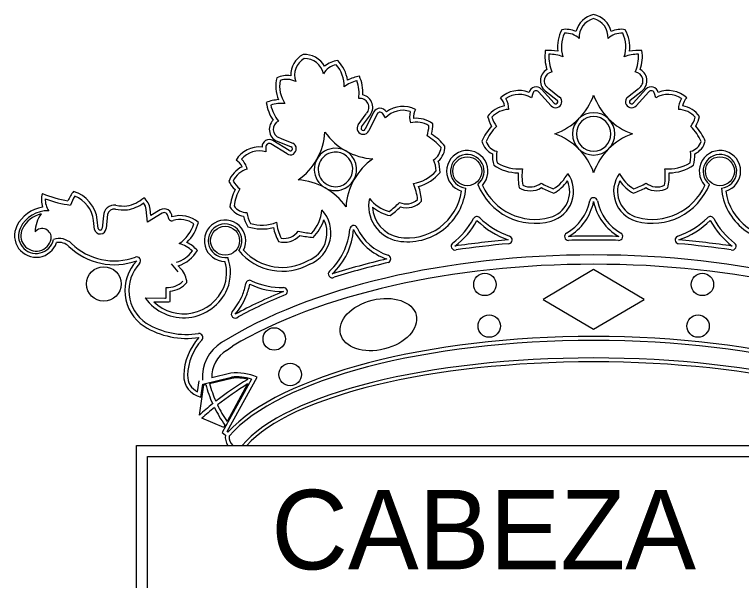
# Model space of a CAD drawing. Extents: x 0.2 to 61.3, y -17.9 to -0.8.
# Drawn here: x 32.52 to 40.48, y -7.03 to -0.84 of the extents above; entities that cross this region are included whole.
import ezdxf

# ---------------------------------------------------------------- set-up
doc = ezdxf.new("R2010")
doc.units = 0
doc.layers.add('Nivel 1', color=7, linetype='Continuous')

msp = doc.modelspace()

# ---------------------------------------------------------------- linework, layer by layer
at = {"layer": 'Nivel 1'}
for p, q in [((38.4267, -1.807), (38.2877, -1.6535)), ((38.3707, -1.6482), (38.4879, -1.7396)), ((39.2317, -1.7396), (39.3489, -1.6482)), ((39.4319, -1.6535), (39.2929, -1.807)), ((38.1935, -1.7018), (38.1784, -1.7493)), ((38.3955, -1.8359), (38.2561, -1.6821)), ((38.3445, -1.6818), (38.4609, -1.7725)), ((39.2586, -1.7725), (39.3751, -1.6818)), ((39.4635, -1.6821), (39.3241, -1.8359)), ((39.5412, -1.7493), (39.5261, -1.7018)), ((36.4532, -1.9053), (36.3611, -2.0907)), ((36.2839, -2.0425), (36.3718, -1.9227)), ((36.3188, -2.0669), (36.4061, -1.9479)), ((36.4913, -1.9242), (36.399, -2.1101)), ((36.5843, -1.9678), (36.5569, -1.9262)), ((35.5274, -2.3261), (35.352, -2.2161)), ((35.4304, -2.1885), (35.5681, -2.2446)), ((35.2745, -2.2882), (35.2729, -2.338)), ((35.5053, -2.3624), (35.3294, -2.2522)), ((35.4144, -2.2279), (35.5511, -2.2836)), ((33.5427, -3.0218), (33.5271, -3.1781)), ((33.9803, -3.1079), (33.9654, -2.9701)), ((34.139, -3.0102), (33.9803, -3.1079)), ((34.0154, -3.0363), (34.0077, -2.9655)), ((34.1166, -2.974), (34.0154, -3.0363)), ((33.399, -3.1867), (33.3875, -3.0881)), ((33.4409, -3.1786), (33.4298, -3.0832)), ((33.498, -3.0404), (33.4847, -3.1738)), ((34.3156, -3.6496), (34.2413, -3.5645)), ((34.3476, -3.6216), (34.3159, -3.5852)), ((38.8598, -3.6272), (38.3068, -3.9523)), ((39.4128, -3.9523), (38.8598, -3.6272)), ((34.1843, -3.937), (34.1843, -3.8215)), ((34.2269, -3.9765), (34.2269, -3.8626)), ((33.9534, -3.9363), (34.1681, -3.9372)), ((38.3068, -3.9523), (38.8598, -4.2775)), ((38.8598, -4.2775), (39.4128, -3.9523)), ((34.0472, -3.9793), (34.1679, -3.9798)), ((34.8436, -4.5104), (34.9084, -4.4629)), ((34.8915, -4.7588), (34.6815, -4.8099)), ((34.5275, -4.9636), (34.5452, -4.8431)), ((34.5831, -4.8777), (34.8987, -4.8008)), ((34.6577, -4.8727), (34.9009, -4.8134)), ((35.1174, -4.8251), (34.7977, -5.4074)), ((34.8517, -5.3975), (35.1782, -4.8028)), ((34.5462, -5.2184), (34.5945, -4.8881)), ((34.5623, -5.0205), (34.5831, -4.8777)), ((34.5945, -4.8881), (34.6163, -4.8828)), ((35.0743, -4.877), (34.8495, -5.2865)), ((34.8134, -5.3523), (34.5736, -5.251)), ((34.8267, -5.3281), (34.8134, -5.3523)), ((34.7977, -5.4074), (34.8309, -5.4357)), ((34.8592, -5.4039), (34.8517, -5.3975)), ((33.8598, -16.2496), (33.8598, -5.5507)), ((33.8598, -5.5507), (38.8598, -5.5507)), ((34.8577, -5.5507), (35.0647, -5.5507)), ((34.9113, -5.5507), (35.0139, -5.5507)), ((38.8598, -5.5507), (43.8598, -5.5507)), ((33.979, -16.2496), (33.979, -5.6699)), ((33.979, -5.6699), (38.8598, -5.6699)), ((38.8598, -5.6699), (43.7406, -5.6699))]:
    msp.add_line(p, q, dxfattribs=at)
for centre, radius in [((37.478, -2.5512), 0.1584), ((40.2416, -2.5512), 0.1584), ((34.828, -3.311), 0.1584), ((33.5008, -3.7837), 0.1891), ((37.6701, -3.7885), 0.1227), ((40.0495, -3.7885), 0.1227), ((37.7177, -4.2436), 0.1227), ((40.0019, -4.2436), 0.1227), ((35.3655, -4.3852), 0.1227), ((35.5396, -4.7737), 0.1227)]:
    msp.add_circle(centre, radius, dxfattribs=at)
for centre, radius, start, end in [((38.9122, -1.0852), 0.2528, 101.96797, 166.02665), ((38.8074, -1.0852), 0.2528, 13.97335, 78.03203), ((38.9122, -1.0852), 0.2102, 104.43964, 183.9233), ((38.8074, -1.0852), 0.2102, 356.0767, 75.56036), ((38.8484, -1.1913), 0.3844, 150.73287, 187.13746), ((38.5576, -1.253), 0.2535, 64.46311, 100.1151), ((39.162, -1.253), 0.2535, 79.8849, 115.53689), ((38.8712, -1.1913), 0.3844, 352.86254, 29.26713), ((38.8484, -1.1913), 0.3418, 154.23185, 198.42348), ((38.5576, -1.253), 0.211, 46.62254, 94.62972), ((39.162, -1.253), 0.211, 85.37028, 133.37746), ((38.8712, -1.1913), 0.3418, 341.57652, 25.76815), ((38.8024, -1.2947), 0.4759, 172.40101, 197.75384), ((38.3738, -1.7056), 0.4757, 78.71145, 95.19619), ((39.3458, -1.7056), 0.4757, 84.80381, 101.28855), ((38.9172, -1.2947), 0.4759, 342.24616, 7.59899), ((35.7987, -1.4996), 0.2528, 117.73147, 181.79015), ((35.7987, -1.4996), 0.2102, 120.20314, 199.68681), ((35.6977, -1.5281), 0.2528, 29.73686, 93.79553), ((35.6977, -1.5281), 0.2102, 11.8402, 91.32386), ((36.0846, -1.5931), 0.2535, 95.6484, 131.30039), ((35.788, -1.6128), 0.3844, 8.62605, 45.03063), ((38.8024, -1.2947), 0.4333, 177.05207, 203.25606), ((38.3738, -1.7056), 0.4331, 69.70422, 90.54379), ((39.3458, -1.7056), 0.4331, 89.45621, 110.29578), ((38.9172, -1.2947), 0.4333, 336.74394, 2.94793), ((36.0846, -1.5931), 0.211, 101.13378, 149.14096), ((35.788, -1.6128), 0.3418, 357.34003, 41.53165), ((35.5029, -1.7573), 0.2535, 80.22661, 115.8786), ((38.4168, -1.5622), 0.1397, 118.90053, 238.8754), ((38.4168, -1.5622), 0.0971, 97.33817, 238.8754), ((39.3028, -1.5622), 0.0971, 301.1246, 82.66183), ((39.3028, -1.5622), 0.1397, 301.1246, 61.09947), ((35.766, -1.619), 0.3844, 166.49637, 202.90096), ((35.766, -1.619), 0.3418, 169.99536, 214.18698), ((35.5029, -1.7573), 0.211, 62.38604, 110.39322), ((36.3844, -1.9788), 0.4331, 105.21971, 126.05928), ((36.3844, -1.9788), 0.4757, 100.56731, 117.05205), ((35.8603, -1.6998), 0.4333, 352.50744, 18.71143), ((35.8603, -1.6998), 0.4759, 358.00966, 23.36249), ((38.0443, -1.9646), 0.2962, 68.51354, 133.41957), ((38.2301, -1.7088), 0.0798, 43.83208, 165.5943), ((39.4895, -1.7088), 0.0798, 14.4057, 136.16792), ((39.6753, -1.9646), 0.2962, 46.58043, 111.48646), ((36.3041, -1.8524), 0.1397, 316.88811, 76.86297), ((37.729, -1.8627), 0.1591, 9.23351, 45.41392), ((38.0443, -1.9646), 0.2537, 58.06833, 124.65139), ((38.2301, -1.7088), 0.0372, 43.83208, 169.19164), ((38.4448, -1.7908), 0.0669, 222.4372, 49.9247), ((38.2071, -1.4896), 0.6915, 289.27044, 340.72956), ((39.5125, -1.4896), 0.6915, 199.27044, 250.72956), ((39.2748, -1.7908), 0.0669, 130.0753, 317.5628), ((39.4895, -1.7088), 0.0372, 10.80836, 136.16792), ((39.6753, -1.9646), 0.2537, 55.34861, 121.93167), ((39.9906, -1.8627), 0.1591, 134.58608, 170.76649), ((35.449, -2.2428), 0.4757, 94.47496, 110.95969), ((35.7499, -1.731), 0.4759, 188.16452, 213.51734), ((35.449, -2.2428), 0.4331, 85.46772, 106.30729), ((35.7499, -1.731), 0.4333, 192.81558, 219.01956), ((36.3041, -1.8524), 0.0971, 316.88811, 98.42534), ((37.729, -1.8627), 0.2017, 356.42911, 31.97613), ((38.4448, -1.7908), 0.0243, 221.73779, 48.52076), ((39.2748, -1.7908), 0.0243, 131.47924, 318.26221), ((39.9906, -1.8627), 0.2017, 148.02387, 183.57089), ((36.5236, -1.9428), 0.0798, 30.16921, 151.93143), ((36.5236, -1.9428), 0.0372, 26.57186, 151.93143), ((36.7719, -2.1385), 0.2537, 71.11211, 137.69518), ((36.7719, -2.1385), 0.2962, 62.34394, 127.24996), ((37.0477, -1.9548), 0.2017, 163.78738, 199.33439), ((37.0477, -1.9548), 0.1591, 150.34958, 186.53), ((37.9384, -2.1314), 0.2988, 100.09223, 142.84596), ((37.9384, -2.1314), 0.2562, 91.81464, 138.26352), ((39.7812, -2.1314), 0.2562, 41.73648, 88.18536), ((39.7812, -2.1314), 0.2988, 37.15404, 79.90777), ((36.9192, -2.2703), 0.2988, 52.91755, 95.67127), ((38.1073, -1.8494), 0.4195, 194.00616, 209.65395), ((38.1073, -1.8494), 0.377, 197.19431, 214.34916), ((38.8598, -2.1423), 0.2316, 90, 270), ((38.8598, -2.1423), 0.1891, 90, 270), ((38.8598, -2.1423), 0.2316, 270, 90), ((38.8598, -2.1423), 0.1891, 270, 90), ((39.6123, -1.8494), 0.377, 325.65084, 342.80569), ((39.6123, -1.8494), 0.4195, 330.34605, 345.99384), ((35.4514, -2.0932), 0.1397, 134.66404, 254.6389), ((35.4514, -2.0932), 0.0971, 113.10167, 254.6389), ((36.3392, -2.0801), 0.0669, 145.83881, 333.3263), ((36.3392, -2.0801), 0.0243, 147.24275, 334.02571), ((36.9192, -2.2703), 0.2562, 57.49999, 103.94886), ((36.68, -2.0448), 0.377, 341.41434, 358.56919), ((36.68, -2.0448), 0.4195, 346.10955, 1.75735), ((38.2089, -2.4676), 0.6213, 138.62593, 156.82666), ((38.2089, -2.4676), 0.5788, 135.51275, 155.29285), ((39.5107, -2.4676), 0.5788, 24.70715, 44.48725), ((39.5107, -2.4676), 0.6213, 23.17334, 41.37407), ((35.2298, -2.0803), 0.6915, 305.03394, 356.49306), ((36.4862, -1.7256), 0.6915, 215.03394, 266.49306), ((36.7501, -2.6674), 0.6213, 38.93684, 57.13757), ((38.2071, -2.795), 0.6915, 19.27044, 70.72956), ((39.5125, -2.795), 0.6915, 109.27044, 160.72956), ((35.3116, -2.285), 0.0798, 59.59558, 181.3578), ((36.7501, -2.6674), 0.5788, 40.47065, 60.25076), ((37.8457, -2.1669), 0.2154, 195.13329, 244.65872), ((37.8457, -2.1669), 0.1728, 199.90196, 254.34899), ((39.8739, -2.1669), 0.1728, 285.65101, 340.09804), ((39.8739, -2.1669), 0.2154, 295.34128, 344.86671), ((35.2022, -2.5816), 0.2962, 84.27704, 149.18307), ((35.3116, -2.285), 0.0372, 59.59558, 184.95514), ((35.5405, -2.3055), 0.0669, 238.20071, 65.6882), ((35.5405, -2.3055), 0.0243, 237.50129, 64.28426), ((36.0354, -2.5311), 0.2316, 285.7635, 105.7635), ((37.018, -2.2793), 0.1728, 301.41452, 355.86154), ((37.018, -2.2793), 0.2154, 311.10478, 0.63021), ((35.2022, -2.5816), 0.2537, 73.83183, 140.41489), ((36.0354, -2.5311), 0.2316, 105.7635, 285.7635), ((36.0354, -2.5311), 0.1891, 105.7635, 285.7635), ((36.0354, -2.5311), 0.1891, 285.7635, 105.7635), ((37.478, -2.5512), 0.2265, 317.09979, 253.8569), ((37.478, -2.5512), 0.1839, 308.80075, 264.91868), ((38.1315, -2.3819), 0.3786, 176.91665, 195.69066), ((38.1315, -2.3819), 0.336, 171.67939, 193.07218), ((39.5881, -2.3819), 0.336, 346.92782, 8.32061), ((39.5881, -2.3819), 0.3786, 344.30934, 3.08335), ((40.2416, -2.5512), 0.2265, 286.1431, 222.90021), ((40.2416, -2.5512), 0.1839, 275.08132, 231.19925), ((34.8711, -2.5692), 0.1591, 24.99701, 61.17742), ((34.8711, -2.5692), 0.2017, 12.19261, 47.73963), ((36.8409, -2.982), 0.6915, 125.03394, 176.49306), ((36.8014, -2.5639), 0.336, 2.69132, 24.08412), ((36.8014, -2.5639), 0.3786, 0.07284, 18.84685), ((38.0361, -2.0957), 0.4301, 237.37214, 276.12885), ((39.6835, -2.0957), 0.4301, 263.87115, 302.62786), ((35.1456, -2.7709), 0.2988, 115.85573, 158.60946), ((35.1456, -2.7709), 0.2562, 107.57815, 154.02702), ((38.0361, -2.0957), 0.4726, 235.30078, 269.76874), ((38.6093, -2.6064), 0.5338, 171.05003, 190.46691), ((39.1103, -2.6064), 0.5338, 349.53309, 8.94997), ((39.6835, -2.0957), 0.4726, 270.23126, 304.69922), ((36.8154, -2.2625), 0.4301, 279.63466, 318.39136), ((36.8154, -2.2625), 0.4726, 285.99477, 320.46273), ((38.6093, -2.6064), 0.5763, 176.21905, 192.47759), ((38.3052, -2.7722), 0.3356, 285.41744, 36.14625), ((38.2017, -2.3853), 0.4195, 301.18985, 333.23645), ((39.4144, -2.7722), 0.3356, 143.85375, 254.58256), ((39.5179, -2.3853), 0.4195, 206.76355, 238.81015), ((39.1103, -2.6064), 0.5763, 347.52241, 3.78095), ((35.2316, -2.4536), 0.4195, 209.76966, 225.41745), ((35.2316, -2.4536), 0.377, 212.95781, 230.11267), ((35.5845, -3.3366), 0.6915, 35.03394, 86.49306), ((36.4025, -2.9097), 0.5338, 5.29659, 24.71347), ((38.2165, -2.4505), 0.6693, 201.38583, 285.41744), ((38.1669, -2.538), 0.1847, 243.48516, 309.79446), ((38.7518, -1.8783), 0.9276, 239.79442, 248.97144), ((38.3052, -2.7722), 0.2931, 285.41744, 23.00372), ((38.2017, -2.3853), 0.462, 298.58927, 323.88397), ((39.4144, -2.7722), 0.2931, 156.99628, 254.58256), ((39.5179, -2.3853), 0.462, 216.11603, 241.41073), ((38.9678, -1.8783), 0.9276, 291.02856, 300.20558), ((39.5031, -2.4505), 0.6693, 254.58256, 338.61417), ((39.5527, -2.538), 0.1847, 230.20554, 296.51484), ((33.5844, -3.0841), 0.5195, 142.97546, 156.20238), ((33.0617, -3.1259), 0.3706, 6.61995, 73.07224), ((35.4974, -3.021), 0.6213, 154.38943, 172.59016), ((35.4974, -3.021), 0.5788, 151.27625, 171.05636), ((36.825, -2.6833), 0.6388, 260.3198, 355.41176), ((36.825, -2.6833), 0.5962, 260.3198, 351.75803), ((36.4025, -2.9097), 0.5763, 3.28591, 19.54445), ((38.2165, -2.4505), 0.6267, 203.99944, 285.41744), ((38.1669, -2.538), 0.2273, 238.04154, 302.1808), ((38.7518, -1.8783), 0.9701, 241.43809, 250.17827), ((38.9678, -1.8783), 0.9701, 289.82173, 298.56191), ((39.5031, -2.4505), 0.6267, 254.58256, 336.00056), ((39.5527, -2.538), 0.2273, 237.8192, 301.95846), ((40.8946, -2.6833), 0.6388, 184.58824, 279.6802), ((40.8946, -2.6833), 0.5962, 188.24197, 279.6802), ((33.0676, -2.8645), 0.2493, 163.50627, 198.77145), ((33.3081, -1.656), 1.2347, 247.14687, 260.72033), ((33.0676, -2.8645), 0.2067, 176.67632, 215.01157), ((33.3081, -1.656), 1.2773, 249.52206, 262.25463), ((33.5844, -3.0841), 0.4769, 146.689, 160.07411), ((33.0617, -3.1259), 0.328, 6.61995, 67.77011), ((33.683, -2.5508), 0.3866, 280.55027, 311.23116), ((33.8286, -2.9849), 0.1802, 6.16871, 52.67285), ((36.788, -2.9299), 0.3896, 167.88821, 259.48609), ((36.7347, -2.5862), 0.4195, 218.64936, 254.57366), ((36.8097, -2.7237), 0.1847, 245.96904, 312.27834), ((38.8598, -2.8829), 0.0426, 90, 168.70348), ((38.8598, -2.8829), 0.0426, 11.29652, 90), ((33.6152, -3.0392), 0.1172, 80.72781, 180.56192), ((33.7302, -2.3347), 0.5967, 260.72781, 272.26578), ((33.683, -2.5508), 0.4292, 280.13507, 306.00592), ((33.8286, -2.9849), 0.1377, 6.16871, 39.13168), ((35.066, -2.8303), 0.2154, 210.8968, 260.42222), ((35.066, -2.8303), 0.1728, 215.66547, 270.11249), ((36.0676, -2.2477), 0.9276, 306.79207, 315.96908), ((36.0676, -2.2477), 0.9701, 305.58523, 314.32541), ((36.8097, -2.7237), 0.2273, 253.5827, 317.72197), ((38.3052, -2.7722), 0.523, 299.52775, 348.70348), ((38.3052, -2.7722), 0.5656, 299.52775, 348.70348), ((39.4144, -2.7722), 0.5656, 191.29652, 240.47225), ((39.4144, -2.7722), 0.523, 191.29652, 240.47225), ((32.8889, -3.3203), 0.3799, 98.6705, 153.19871), ((32.8889, -3.3203), 0.3373, 88.39358, 153.19871), ((32.8889, -3.3203), 0.3117, 103.69997, 153.19871), ((33.084, -3.216), 0.3343, 143.56432, 179.77447), ((33.6152, -3.0392), 0.0746, 80.72781, 166.45195), ((33.7302, -2.3347), 0.6393, 260.72781, 272.53965), ((34.1613, -3.0466), 0.0852, 357.87186, 121.6139), ((34.1613, -3.0466), 0.0426, 357.87186, 121.6139), ((35.3996, -2.9596), 0.336, 187.44289, 208.83568), ((35.6191, -3.2254), 0.3664, 291.52971, 43.15422), ((35.468, -2.9438), 0.4195, 316.95335, 355.75073), ((36.788, -2.9299), 0.347, 182.17801, 259.48609), ((36.7347, -2.5862), 0.462, 230.57378, 257.17423), ((34.2465, -3.0497), 0.0426, 177.87186, 286.8581), ((34.336, -3.3451), 0.3086, 49.43343, 106.8581), ((34.336, -3.3451), 0.266, 55.25114, 106.8581), ((34.828, -3.311), 0.2265, 332.89958, 269.62617), ((35.3996, -2.9596), 0.3786, 192.68016, 211.45416), ((35.6191, -3.2254), 0.3238, 291.52971, 26.40349), ((35.468, -2.9438), 0.462, 314.35277, 342.66379), ((36.825, -2.6833), 0.8176, 307.03794, 331.85159), ((36.825, -2.6833), 0.8602, 307.03794, 331.85159), ((37.5834, -3.0891), 0.0426, 45.25182, 151.85159), ((38.2165, -2.4505), 0.8992, 225.25182, 251.16555), ((38.2165, -2.4505), 0.8566, 225.25182, 251.16555), ((39.5031, -2.4505), 0.8566, 288.83445, 314.74818), ((39.5031, -2.4505), 0.8992, 288.83445, 314.74818), ((40.1362, -3.0891), 0.0426, 28.14841, 134.74818), ((40.8946, -2.6833), 0.8602, 208.14841, 232.96206), ((40.8946, -2.6833), 0.8176, 208.14841, 232.96206), ((32.7608, -3.2556), 0.2364, 153.19871, 341.19359), ((32.7608, -3.2556), 0.1938, 153.19871, 347.77983), ((32.7608, -3.2556), 0.1682, 153.19871, 347.77983), ((32.8269, -3.2771), 0.0993, 351.87907, 141.00072), ((33.4623, -3.1716), 0.0651, 193.38536, 354.30102), ((33.4623, -3.1716), 0.0225, 198.13823, 354.30102), ((34.0854, -2.9931), 0.4238, 304.61006, 341.65185), ((34.0854, -2.9931), 0.4664, 313.88616, 345.40033), ((34.828, -3.311), 0.1839, 324.21574, 278.81736), ((35.23, -2.7101), 0.4726, 251.06428, 285.53224), ((35.23, -2.7101), 0.4301, 253.13564, 291.89235), ((35.9203, -3.0458), 0.5763, 191.98255, 208.24109), ((35.9203, -3.0458), 0.5338, 186.81354, 206.23041), ((36.234, -3.1875), 0.0426, 24.93945, 175.9622), ((36.788, -2.9299), 0.5684, 204.93945, 251.87), ((35.476, -3.1002), 0.2273, 253.80504, 317.9443), ((35.476, -3.1002), 0.1847, 259.24866, 325.55796), ((35.8597, -2.3064), 0.9276, 255.55792, 264.73494), ((35.8597, -2.3064), 0.9701, 257.2016, 265.94177), ((35.5066, -3.1362), 0.6867, 312.51796, 355.9622), ((35.5066, -3.1362), 0.7293, 312.51796, 355.9622), ((36.788, -2.9299), 0.611, 204.93945, 251.87), ((38.5839, -3.2643), 0.0426, 119.52775, 272.97441), ((39.1357, -3.2643), 0.0426, 267.02559, 60.47225), ((33.0116, -3.4845), 0.1977, 46.03866, 108.09412), ((33.0116, -3.4845), 0.1552, 46.03866, 100.0449), ((34.2209, -3.697), 0.4129, 42.67243, 62.95816), ((37.3431, -3.37), 0.0426, 127.03794, 286.57568), ((37.9262, -3.3016), 0.0426, 280.11402, 71.16555), ((39.7934, -3.3016), 0.0426, 108.83445, 259.88598), ((40.3765, -3.37), 0.0426, 253.42432, 52.96206), ((33.6159, -2.858), 0.7153, 226.03865, 290.05151), ((33.6159, -2.858), 0.6727, 226.03865, 290.05151), ((34.1923, -3.2184), 0.3871, 288.60985, 329.10954), ((34.2209, -3.697), 0.3704, 47.79032, 73.50657), ((35.4538, -3.0289), 0.6157, 219.27118, 299.71252), ((35.4538, -3.0289), 0.5731, 222.2527, 299.71252), ((33.8611, -3.5299), 0.0426, 316.5512, 110.05151), ((34.1923, -3.2184), 0.3446, 287.81719, 323.62915), ((34.4174, -3.6609), 0.4699, 337.67084, 20.9603), ((36.5979, -3.5105), 0.0426, 295.17919, 71.87), ((34.2035, -3.8543), 0.4716, 136.5512, 236.20466), ((34.2035, -3.8543), 0.429, 136.5512, 236.1052), ((34.4174, -3.6609), 0.4273, 337.67084, 16.7768), ((34.1518, -3.7926), 0.26, 5.27494, 41.11863), ((35.9994, -3.6737), 0.0426, 132.51796, 302.54915), ((34.1953, -3.5739), 0.2478, 267.45923, 313.44867), ((34.1953, -3.5739), 0.2904, 276.24572, 317.8765), ((34.4174, -3.6609), 0.6487, 337.47228, 349.55579), ((35.0972, -3.7862), 0.0426, 64.78508, 169.55579), ((34.4174, -3.6609), 0.6913, 337.44843, 349.55579), ((35.4538, -3.0289), 0.8371, 244.78508, 270.875), ((35.4538, -3.0289), 0.7945, 244.78508, 270.875), ((34.3753, -3.6332), 0.5194, 215.69717, 336.51775), ((34.3753, -3.6332), 0.4768, 226.52798, 336.51775), ((35.4666, -3.8659), 0.0426, 309.66095, 90.875), ((34.1699, -3.4866), 0.4506, 269.76535, 271.82593), ((34.3753, -3.6332), 0.6983, 319.48064, 336.69892), ((34.3753, -3.6332), 0.7408, 319.48064, 336.72112), ((34.1699, -3.4866), 0.4932, 269.76115, 276.62945), ((34.9384, -4.1146), 0.0426, 139.48064, 317.5264), ((34.4057, -3.4961), 0.8397, 238.28372, 279.06105), ((34.4057, -3.4961), 0.8822, 238.23173, 278.85133), ((35.0261, -4.8028), 0.6513, 138.09648, 177.93742), ((34.5414, -4.3678), 0.0426, 316.1093, 94.72329), ((35.0261, -4.8028), 0.6087, 138.23555, 177.93742), ((35.0261, -4.8028), 0.4469, 121.98086, 184.06795), ((35.0261, -4.8028), 0.3447, 121.98086, 181.17517), ((34.9514, -5.3235), 0.5679, 66.4667, 96.0602), ((34.6131, -4.788), 0.238, 177.93742, 257.65352), ((34.6131, -4.788), 0.1954, 177.93742, 244.02028), ((36.8226, -7.7398), 3.397, 120.94451, 128.1035), ((34.9514, -5.3235), 0.5253, 71.58282, 95.75659), ((34.9514, -5.3235), 0.5126, 75.94778, 95.6582), ((35.959, -4.5209), 1.3906, 195.08209, 204.33906), ((35.959, -4.5209), 1.348, 195.12611, 203.88282), ((36.8226, -7.7398), 3.3544, 121.41255, 128.27536), ((36.8226, -7.7398), 3.397, 128.84484, 132.07695), ((36.8226, -7.7398), 3.3544, 129.02089, 132.10414), ((35.959, -4.5209), 1.3906, 206.14483, 215.48457), ((35.959, -4.5209), 1.348, 205.74318, 214.60833), ((35.0135, -5.4537), 0.1835, 174.39177, 211.92161), ((35.0135, -5.4537), 0.1409, 177.2857, 223.51601)]:
    msp.add_arc(centre, radius, start, end, dxfattribs=at)
for major_axis, ratio, start_param, end_param in [((5.3165, 0), 0.494541, 1.747319, 1.860097), ((5.3165, 0), 0.494541, 1.570796, 1.62271), ((5.2739, 0), 0.49046, 1.570796, 1.62271), ((-5.3165, 0), 0.494541, 4.660476, 4.712389), ((-5.2739, 0), 0.49046, 4.660476, 4.712389), ((-5.3165, 0), 0.494541, 4.423089, 4.535866), ((5.2739, 0), 0.49046, 1.747319, 1.860097), ((-5.2739, 0), 0.49046, 4.423089, 4.535866), ((5.1113, 0), 0.474252, 1.570796, 2.492022), ((-5.1113, 0), 0.474252, 3.791163, 4.712389), ((5.0091, 0), 0.463527, 1.570796, 2.479733), ((5.3165, 0), 0.494541, 2.010256, 2.138886), ((5.2739, 0), 0.49046, 2.010256, 2.138886), ((-5.0091, 0), 0.463527, 3.803452, 4.712389), ((5.3165, 0), 0.494541, 2.263011, 2.400288), ((5.2739, 0), 0.49046, 2.263011, 2.400288), ((4.2187, 0), 0.363017, 1.570796, 2.818645), ((-4.2187, 0), 0.363017, 3.46454, 4.712389), ((4.1761, 0), 0.356522, 1.570796, 2.839524), ((-4.1761, 0), 0.356522, 3.443662, 4.712389), ((3.9845, 0), 0.325579, 1.570796, 2.877004), ((-3.9845, 0), 0.325579, 3.406181, 4.712389), ((3.942, 0), 0.318294, 1.570796, 2.867798), ((-3.942, 0), 0.318294, 3.415388, 4.712389)]:
    msp.add_ellipse((38.8598, -5.8899), major_axis=major_axis, ratio=ratio, start_param=start_param, end_param=end_param, dxfattribs=at)
msp.add_ellipse((36.5048, -4.2272), major_axis=(-0.4136, -0.1036), ratio=0.645239, dxfattribs=at)

# ---------------------------------------------------------------- texts
msp.add_text('CABEZA', height=0.86862, dxfattribs=at).set_placement((35.3328, -6.9034))

doc.saveas('drawing.dxf')
